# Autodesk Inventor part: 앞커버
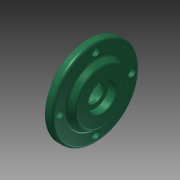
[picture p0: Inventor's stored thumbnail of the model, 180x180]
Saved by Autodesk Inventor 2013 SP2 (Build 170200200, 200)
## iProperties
Created: 2015-11
Part Number: 앞커버
Material: 알루미늄 6061
Document SubType Name: Modeling
Designer: mduedu
Density: 2.71 g/cm^3
Author: mduedu
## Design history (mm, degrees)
sketch "스케치1"
  geometry: C1 r 47.5 at (0, 0); 1 further point
  constraints: 1 centre point, 1 coincident
  dimensions: "d57" = 95 diameter of C1
extrude "돌출1" new body sketch "스케치1" distance "d3" = 8; taper "d4" = 0 deg
sketch "스케치2"
  geometry: C1 r 32.5 at (0, 0); 1 further point
  constraints: 1 centre point, 1 coincident
  dimensions: "d5" = 65 diameter of C1
extrude "돌출2" join sketch "스케치2" distance "d6" = 7; taper "d7" = -30 deg
sketch "스케치3" dims "d58" = 78
  geometry: 3 further points
  constraints: 2 vertical alignment, 1 coincident, 2 other
hole "구멍1" sketch "스케치3" at (0, 39) diameter "d11" = 4.5; stored, may be unused: countersink angle "d15" = 90 deg, drill point angle "d17" = 118 deg; dims "d12" = 6, "d13" = 8, "d14" = 4.4, "d16" = 8
sketch "스케치4"
  geometry: C1 r 32.5 at (0, 0); 1 further point
  constraints: 1 centre point, 1 coincident
  dimensions: "d21" = 65 diameter of C1
extrude "돌출3" join sketch "스케치4" distance "d23" = 12; taper "d24" = 0 deg
hole "구멍2" diameter "d27" = 34; stored, may be unused: countersink angle "d31" = 90 deg, drill point angle "d33" = 0 deg; dims "d28" = 6, "d29" = 40, "d30" = 12, "d32" = 15, "d65" = 10, "d66" = 10
fillet "모깎기3" dims "d36" = 3
fillet "모깎기4" dims "d37" = 3
fillet "모깎기5" dims "d38" = 0.3
chamfer "모따기1" distance "d39" = 1; stored, may be unused: second distance "d40" = 2, angle "d41" = 45 deg
hole "구멍3" diameter "d44" = 20; stored, may be unused: countersink angle "d48" = 90 deg, drill point angle "d50" = 118 deg; dims "d45" = 6, "d46" = 30, "d47" = 8.3, "d49" = 8, "d59" = 10, "d60" = 10
fillet "모깎기6" dims "d51" = 0.3
chamfer "모따기2" distance "d52" = 0.8; stored, may be unused: second distance "d53" = 2, angle "d54" = 30 deg
node "솔리드1"
pattern_circular "원형 패턴1" dims angle "d19" = 360 deg
